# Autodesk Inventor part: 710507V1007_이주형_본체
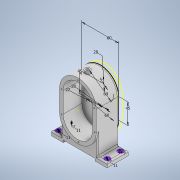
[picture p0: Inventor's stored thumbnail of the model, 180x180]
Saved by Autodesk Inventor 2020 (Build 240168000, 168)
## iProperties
Created: 2021-05
Part Number: 710507V1007_이주형_본체
Material: 일반
Document SubType Name: Modeling
Designer: Owner
Density: 1 g/cm^3
Appearance: 기본값
Author: Owner
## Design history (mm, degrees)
sketch "스케치1"
  geometry: L1 (0, 22.5)-(0, -22.5); L2 (-40, 22.5)-(-40, -22.5); L3 (40, -22.5)-(40, 22.5); L4 (-30, 22.5)-(-30, -22.5); L5 (30, 22.5)-(30, -22.5); L6 (30, -7.5)-(-30, -7.5); A1 r 40 centre (0, 22.5) between (40, 22.5) and (-40, 22.5); A2 r 40 centre (0, -22.5) between (-40, -22.5) and (40, -22.5); A3 r 30 centre (0, 22.5) between (30, 22.5) and (-30, 22.5); A4 r 30 centre (0, -22.5) between (-30, -22.5) and (30, -22.5); 2 further points
  constraints: 14 end point, 8 point on circle, 6 tangent, 4 centre point, 2 point on line, 2 vertical, 1 coincident, 1 midpoint, 1 parallel, 1 perpendicular
  dimensions: "d2" = 80 distance between parallel lines of L3 L2; "d4" = 45 distance of L3.start L3.end; "d9" = 60 diameter of A3; "d10" = 60 diameter of A4
extrude "돌출1" new body sketch "스케치1" distance "d5" = 49; taper "d6" = 0 deg
feature "쉘1" dims "d7" = 8
sketch "스케치2"
  geometry: 1 further point
sketch "스케치3"
  geometry: 1 further point
sketch "스케치5"
  geometry: 1 further point
extrude "돌출3" join sketch "스케치1" distance "d18" = 8; taper "d19" = 0 deg
sketch "스케치6"
  geometry: 1 further point
sketch "스케치7"
  geometry: 1 further point
sketch "스케치8"
  geometry: L1 (30, 22.5)-(30, -7.5) reference; L2 (30, -7.5)-(-30, -7.5) reference; L3 (-30, -7.5)-(-30, 22.5) reference; L4 (40, 22.5)-(40, -22.5) reference; L5 (-40, -22.5)-(-40, 22.5) reference; C1 r 14 at (0, 22.5); C2 r 11 at (0, 22.5); C3 r 14 at (0, -22.5); C4 r 11 at (0, -22.5); A1 r 30 centre (0, 22.5) between (30, 22.5) and (-30, 22.5) reference; A2 r 30 centre (0, 22.5) between (30, 22.5) and (-30, 22.5) reference; A3 r 40 centre (0, 22.5) between (40, 22.5) and (-40, 22.5) reference; A4 r 40 centre (0, -22.5) between (-40, -22.5) and (40, -22.5) reference; 1 further point
  constraints: 4 centre point, 3 coincident
  dimensions: "d20" = 28 diameter of C1; "d21" = 22 diameter of C2; "d22" = 22 diameter of C4; "d23" = 28 diameter of C3; "d24" = 45 distance of C1.centre C3.centre
  node "투영된 루프1"
extrude "돌출4" cut sketch "스케치8" distance "d25" = 4; taper "d26" = 0 deg
extrude "돌출5" cut sketch "스케치8" distance "d27" = 18.5; taper "d28" = 0 deg
sketch "스케치9"
  geometry: C1 r 14 at (0, 45.001); 1 further point
  constraints: 1 centre point
  dimensions: "d29" = 28 diameter of C1
extrude "돌출6" cut sketch "스케치9" distance "d30" = 8; taper "d31" = 0 deg
sketch "스케치10"
  geometry: L1 (-30, 22.5)-(-30, -22.5) reference; L2 (30, 22.5)-(30, -22.5) reference; A1 r 30 centre (0, -22.5) between (-30, -22.5) and (30, -22.5) reference; 1 further point
sketch "스케치11"
  geometry: L1 (35, -69.5)-(61, -69.5); L2 (61, -69.5)-(61, -79.5); L3 (61, -79.5)-(35, -79.5); L4 (35, -79.5)-(35, -69.5); L5 (40, 22.5)-(40, -22.5) reference; L6 (40, -22.5)-(0, -22.5); L7 (0, -74.5)-(40, -74.5); L8 (40, -74.5)-(40, -22.5); L9 (0, -74.5)-(0, -62.5); A1 r 40 centre (0, 22.5) between (40, 22.5) and (-40, 22.5) reference; A2 r 40 centre (0, -22.5) between (-40, -22.5) and (40, -22.5) reference; 3 further points
  constraints: 16 end point, 3 parallel, 2 horizontal, 1 perpendicular, 1 point on circle, 1 vertical
  dimensions: "d32" = 10 distance of L1.end L2.end; "d33" = 26 distance of L2.end L3.end; "d35" = 92 vertical distance of A1.centre L1.start
sketch "스케치12"
  geometry: 1 further point
sketch "스케치13"
  geometry: 1 further point
extrude "돌출7" join sketch "스케치11" distance "d36" = 46; taper "d37" = 0 deg
fillet "모깎기1" dims "d38" = 3
node "작업 평면2"
sketch "스케치14"
  geometry: L1 (40, 49)-(-40, 49) reference; C1 r 6 at (0, 28); 1 further point
  constraints: 1 centre point
  dimensions: "d40" = 21 distance from line of L1 C1.centre; "d41" = 12 diameter of C1
sketch "스케치15"
  geometry: 1 further point
extrude "돌출8" join sketch "스케치14" stored distance "d42" = 3; taper "d43" = 0 deg
sketch "스케치16"
  geometry: C1 r 3 at (0, 0); 1 further point
  constraints: 1 centre point
  dimensions: "d44" = 6 diameter of C1
extrude "돌출9" cut sketch "스케치16" distance "d45" = 18.5; taper "d46" = 0 deg
fillet "모깎기2" dims "d47" = 3
sketch "스케치17"
  geometry: C1 r 5.5 at (-4.828, 33.655); C2 r 5.5 at (-4.828, 4.974); C3 r 3.5 at (-4.828, 33.655); C4 r 3.5 at (-4.828, 4.974); C5 r 5.5 at (-111.315, 33.655); C6 r 5.5 at (-111.315, 4.974); C7 r 3.5 at (-111.315, 33.655); C8 r 3.5 at (-111.315, 4.974); 1 further point
  constraints: 8 centre point, 4 coincident
  dimensions: "d48" = 11 diameter of C1; "d49" = 11 diameter of C2; "d51" = 7 diameter of C3; "d52" = 7 diameter of C4; "d53" = 11 diameter of C5; "d54" = 11 diameter of C6; "d55" = 7 diameter of C7; "d56" = 7 diameter of C8
extrude "돌출10" cut sketch "스케치17" distance "d57" = 15; taper "d58" = 0 deg
extrude "돌출11" cut sketch "스케치17" distance "d59" = 2; taper "d60" = 0 deg
sketch "스케치18"
  geometry: L1 (0, 57.76)-(0, -58.75); L2 (-37, 20.76)-(-37, -21.75); L3 (37, -21.75)-(37, 20.76); A1 r 37 centre (0, 20.76) between (37, 20.76) and (-37, 20.76); A2 r 37 centre (0, -21.75) between (-37, -21.75) and (37, -21.75); 3 further points
  constraints: 8 end point, 6 point on circle, 4 tangent, 2 centre point, 2 point on line, 1 coincident, 1 midpoint, 1 parallel, 1 vertical
hole "구멍1" sketch "스케치18" at (0, 57.76) diameter "d61" = 2.459; stored, may be unused: countersink angle "d65" = 90 deg, drill point angle "d67" = 118 deg; dims "d62" = 8, "d63" = 4, "d64" = 2, "d66" = 10
sketch "스케치19"
  geometry: 6 further points
hole "구멍2" sketch "스케치19" at (35.952, 22.733), (36.687, -22.459), (1.415, -59.201), (-35.695, -25.031), (-35.695, 23.101) diameter "d68" = 2.459; stored, may be unused: countersink angle "d72" = 90 deg, drill point angle "d74" = 118 deg; dims "d69" = 8, "d70" = 4, "d71" = 2, "d73" = 10
node "솔리드1"
mirror "미러1"
node "작업 평면1"
feature "A9D066F2-1C7D-4E18-AEED-F7BC21143FA4" dims "d61" = 2.459, "d62" = 8, "d63" = 4, "d64" = 2, "d65" = 90 deg, "d66" = 10, "d67" = 118 deg
other parameters: "d39" = 67.5
